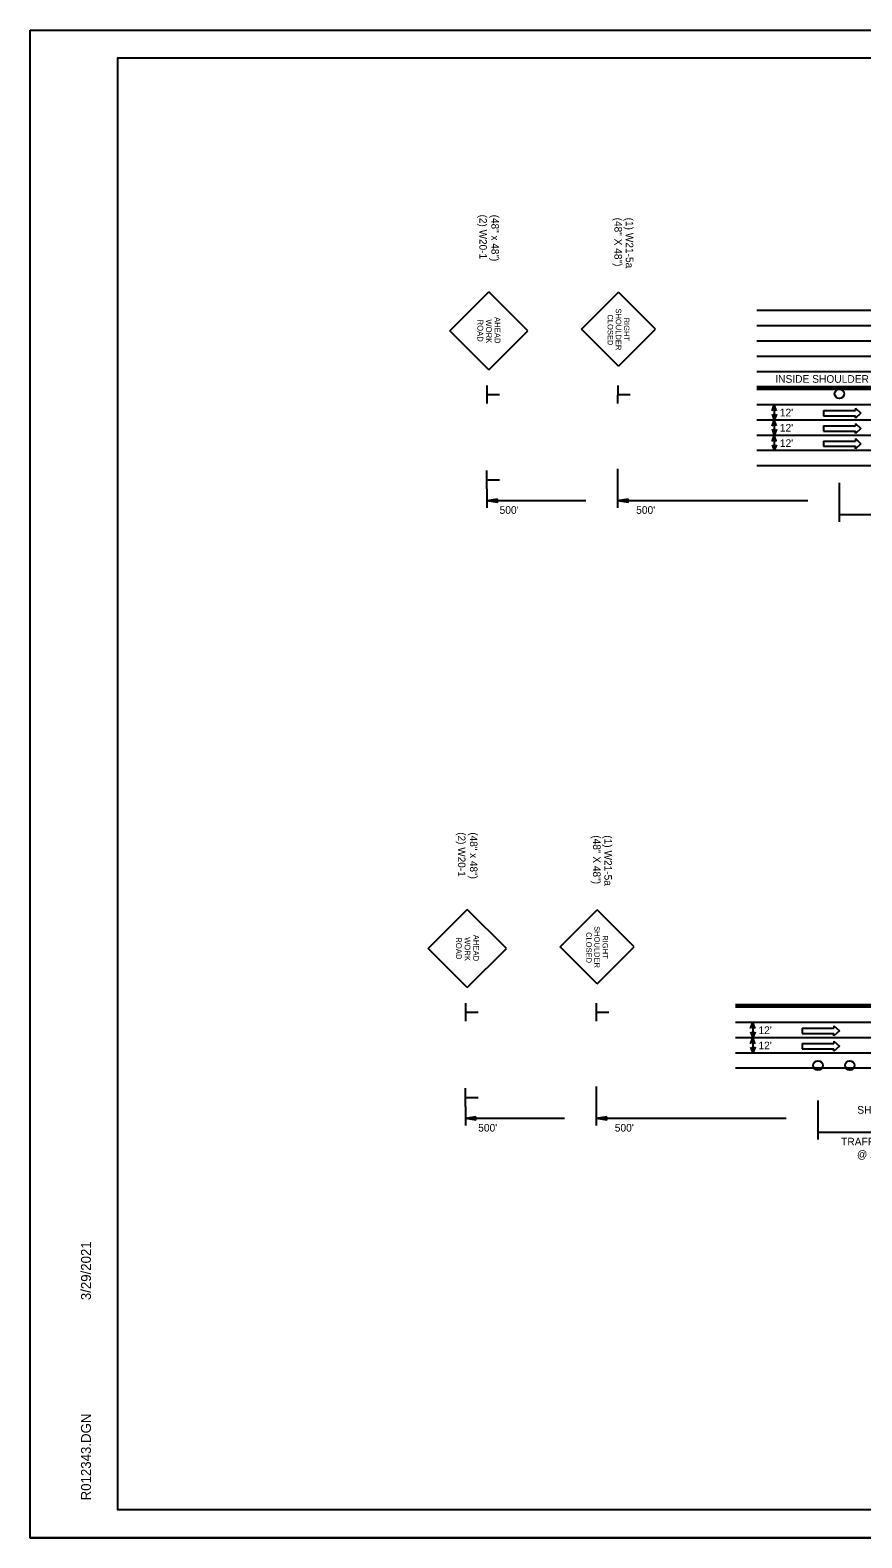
# Model space of a CAD drawing. Extents: x 1397271 to 1411271, y 376395 to 377888.
# Drawn here: x 1408938 to 1409762, y 376395 to 377888 of the extents above; entities that cross this region are included whole.
import ezdxf

# ---------------------------------------------------------------- set-up
doc = ezdxf.new("R2010")
doc.units = 0
for name, color, linetype in [('Default', 7, 'Continuous'), ('R_Border', 7, 'Continuous'), ('R_Dimension', 7, 'Continuous'), ('R_Horz Alg', 7, 'Continuous'), ('R_MOT', 7, 'Continuous'), ('R_No Plot', 7, 'Continuous')]:
    doc.layers.add(name, color=color, linetype=linetype)

msp = doc.modelspace()

# ---------------------------------------------------------------- linework, layer by layer
at = {"layer": 'Default'}
for p, q in [((1409400.8, 377423.3), (1409390.5, 377421.7)), ((1409400.8, 377420.2), (1409390.5, 377421.7)), ((1409400.8, 377423.1), (1409392.2, 377421.7)), ((1409400.8, 377420.5), (1409392.2, 377421.7)), ((1409400.8, 377422.8), (1409394, 377421.8)), ((1409400.8, 377420.8), (1409394, 377421.8)), ((1409400.8, 377422.6), (1409395.7, 377421.8)), ((1409400.8, 377421), (1409395.7, 377421.8)), ((1409400.8, 377422.3), (1409397.4, 377421.8)), ((1409400.8, 377421.3), (1409397.4, 377421.8)), ((1409400.8, 377422), (1409399.2, 377421.8)), ((1409400.8, 377421.6), (1409399.2, 377421.8)), ((1409400.8, 377420.2), (1409400.8, 377423.3)), ((1409530.3, 377423.3), (1409519.9, 377421.7)), ((1409530.3, 377420.2), (1409519.9, 377421.7)), ((1409530.3, 377423.1), (1409521.7, 377421.7)), ((1409530.3, 377420.5), (1409521.7, 377421.7)), ((1409530.3, 377422.8), (1409523.5, 377421.8)), ((1409530.3, 377420.8), (1409523.5, 377421.8)), ((1409530.3, 377422.6), (1409525.2, 377421.8)), ((1409530.3, 377421), (1409525.2, 377421.8)), ((1409530.3, 377422.3), (1409526.9, 377421.8)), ((1409530.3, 377421.3), (1409526.9, 377421.8)), ((1409530.3, 377422), (1409528.7, 377421.8)), ((1409530.3, 377421.6), (1409528.7, 377421.8)), ((1409530.3, 377420.2), (1409530.3, 377423.3)), ((1409379.6, 376811.5), (1409369.3, 376809.9)), ((1409379.6, 376808.4), (1409369.3, 376809.9)), ((1409379.6, 376811.3), (1409371, 376809.9)), ((1409379.6, 376808.7), (1409371, 376809.9)), ((1409379.6, 376811), (1409372.8, 376809.9)), ((1409379.6, 376809), (1409372.8, 376809.9)), ((1409379.6, 376810.8), (1409374.5, 376810)), ((1409379.6, 376809.2), (1409374.5, 376810)), ((1409379.6, 376810.5), (1409376.2, 376810)), ((1409379.6, 376809.5), (1409376.2, 376810)), ((1409379.6, 376810.2), (1409378, 376810)), ((1409379.6, 376809.7), (1409378, 376810)), ((1409379.6, 376808.4), (1409379.6, 376811.5)), ((1409509.1, 376811.5), (1409498.7, 376809.9)), ((1409509.1, 376808.4), (1409498.7, 376809.9)), ((1409509.1, 376811.3), (1409500.5, 376809.9)), ((1409509.1, 376808.7), (1409500.5, 376809.9)), ((1409509.1, 376811), (1409502.2, 376809.9)), ((1409509.1, 376809), (1409502.2, 376809.9)), ((1409509.1, 376810.8), (1409504, 376810)), ((1409509.1, 376809.2), (1409504, 376810)), ((1409509.1, 376810.5), (1409505.7, 376810)), ((1409509.1, 376809.5), (1409505.7, 376810)), ((1409509.1, 376810.2), (1409507.4, 376810)), ((1409509.1, 376809.7), (1409507.4, 376810)), ((1409509.1, 376808.4), (1409509.1, 376811.5))]:
    msp.add_line(p, q, dxfattribs=at)
at = {"layer": 'R_Border'}
for p, q in [((1409024.8, 377860.7), (1411238.1, 377860.7)), ((1409024.8, 376422.5), (1409024.8, 377860.7)), ((1409024.8, 376422.5), (1409024.8, 376422.5)), ((1411238.1, 376422.5), (1409024.8, 376422.5))]:
    msp.add_line(p, q, dxfattribs=at)
at = {"layer": 'R_Dimension'}
for p, q in [((1409673, 377511), (1409675.1, 377516.9)), ((1409675.1, 377516.9), (1409675.1, 377471.5)), ((1409677.3, 377511), (1409675.1, 377516.9)), ((1409672.9, 377507.7), (1409675.1, 377501.8)), ((1409673, 377495.8), (1409675.1, 377501.8)), ((1409677.2, 377507.7), (1409675.1, 377501.8)), ((1409677.3, 377495.9), (1409675.1, 377501.8)), ((1409672.9, 377492.6), (1409675.1, 377486.6)), ((1409673, 377480.7), (1409675.1, 377486.6)), ((1409677.2, 377492.6), (1409675.1, 377486.6)), ((1409677.3, 377480.7), (1409675.1, 377486.6)), ((1409672.9, 377477.4), (1409675.1, 377471.5)), ((1409677.2, 377477.4), (1409675.1, 377471.5)), ((1409519.9, 377453.4), (1409519.9, 377414.9)), ((1409739.5, 377439.7), (1409739.5, 377401.1)), ((1409390.5, 377433.8), (1409390.5, 377414.9)), ((1409488.4, 377421.7), (1409390.5, 377421.7)), ((1409708.2, 377421.7), (1409519.9, 377421.7)), ((1410117.6, 377408), (1409739.5, 377408)), ((1409651.7, 376899.2), (1409653.9, 376905.1)), ((1409653.9, 376905.1), (1409653.9, 376874.8)), ((1409656.1, 376899.2), (1409653.9, 376905.1)), ((1409651.7, 376895.9), (1409653.9, 376890)), ((1409651.7, 376884), (1409653.9, 376890)), ((1409656, 376895.9), (1409653.9, 376890)), ((1409656.1, 376884), (1409653.9, 376890)), ((1409651.7, 376880.7), (1409653.9, 376874.8)), ((1409656, 376880.8), (1409653.9, 376874.8)), ((1409498.7, 376841.6), (1409498.7, 376803.1)), ((1409718.3, 376827.9), (1409718.3, 376789.3)), ((1409369.3, 376822), (1409369.3, 376803.1)), ((1409467.2, 376809.9), (1409369.3, 376809.9)), ((1409687, 376809.9), (1409498.7, 376809.9)), ((1410373.8, 376796.2), (1409718.3, 376796.2))]:
    msp.add_line(p, q, dxfattribs=at)
at = {"layer": 'R_Horz Alg'}
for p, q in [((1410680, 377610.2), (1409657.9, 377610.2)), ((1410680, 377595.1), (1409657.9, 377595.1)), ((1410680, 377579.9), (1409657.9, 377579.9)), ((1410680, 377564.8), (1409657.9, 377564.8)), ((1410680, 377549.7), (1409657.9, 377549.7)), ((1409991.6, 377534.6), (1409657.9, 377534.6)), ((1410680, 377533.3), (1409657.9, 377533.3)), ((1409991.6, 377532), (1409657.9, 377532)), ((1410680, 377516.9), (1409657.9, 377516.9)), ((1410680, 377501.8), (1409657.9, 377501.8)), ((1410680, 377486.6), (1409657.9, 377486.6)), ((1410680, 377471.5), (1409657.9, 377471.5)), ((1410680, 377456.4), (1409657.9, 377456.4)), ((1409970.4, 376922.7), (1409636.7, 376922.7)), ((1410658.8, 376921.5), (1409636.7, 376921.5)), ((1409970.4, 376920.2), (1409636.7, 376920.2)), ((1410658.8, 376905.1), (1409636.7, 376905.1)), ((1410658.8, 376890), (1409636.7, 376890)), ((1410658.8, 376874.8), (1409636.7, 376874.8)), ((1410091.5, 376859.7), (1409636.7, 376859.7))]:
    msp.add_line(p, q, dxfattribs=at)
at = {"layer": 'R_MOT'}
for p, q in [((1409353.6, 377590.2), (1409392.3, 377628.8)), ((1409430.9, 377590.2), (1409392.3, 377628.8)), ((1409484.3, 377591.9), (1409520.9, 377628.6)), ((1409557.6, 377591.9), (1409520.9, 377628.6)), ((1409392.3, 377551.5), (1409353.6, 377590.2)), ((1409392.3, 377551.5), (1409430.9, 377590.2)), ((1409520.9, 377555.3), (1409484.3, 377591.9)), ((1409520.9, 377555.3), (1409557.6, 377591.9)), ((1409390.5, 377536), (1409390.4, 377518.1)), ((1409520, 377536), (1409519.9, 377518.1)), ((1409390.4, 377527.1), (1409402.9, 377527)), ((1409520, 377527.1), (1409532.5, 377527)), ((1409723.9, 377511.1), (1409755.4, 377511.1)), ((1409723.9, 377511.1), (1409723.9, 377506.1)), ((1409723.9, 377506.1), (1409755.4, 377506.1)), ((1409755.4, 377513.6), (1409760.9, 377508.6)), ((1409755.4, 377513.6), (1409755.4, 377511.1)), ((1409760.9, 377508.6), (1409755.4, 377503.6)), ((1409755.4, 377503.6), (1409755.4, 377506.1)), ((1409723.9, 377496), (1409755.4, 377496)), ((1409723.9, 377496), (1409723.9, 377490.9)), ((1409723.9, 377490.9), (1409755.4, 377490.9)), ((1409755.4, 377498.5), (1409760.9, 377493.5)), ((1409755.4, 377498.5), (1409755.4, 377496)), ((1409760.9, 377493.5), (1409755.4, 377488.4)), ((1409755.4, 377488.4), (1409755.4, 377490.9)), ((1409723.9, 377480.9), (1409755.4, 377480.9)), ((1409723.9, 377480.9), (1409723.9, 377475.8)), ((1409723.9, 377475.8), (1409755.4, 377475.8)), ((1409755.4, 377483.4), (1409760.9, 377478.3)), ((1409755.4, 377483.4), (1409755.4, 377480.9)), ((1409760.9, 377478.3), (1409755.4, 377473.3)), ((1409755.4, 377473.3), (1409755.4, 377475.8)), ((1409390.5, 377433.8), (1409390.4, 377451.7)), ((1409390.4, 377442.7), (1409402.9, 377442.7)), ((1409332.4, 376978.4), (1409371, 377017)), ((1409409.7, 376978.4), (1409371, 377017)), ((1409463.1, 376980.1), (1409499.7, 377016.7)), ((1409536.4, 376980.1), (1409499.7, 377016.7)), ((1409371, 376939.7), (1409332.4, 376978.4)), ((1409371, 376939.7), (1409409.7, 376978.4)), ((1409499.7, 376943.4), (1409463.1, 376980.1)), ((1409499.7, 376943.4), (1409536.4, 376980.1)), ((1409369.3, 376924.2), (1409369.2, 376906.3)), ((1409498.8, 376924.2), (1409498.7, 376906.3)), ((1409369.2, 376915.3), (1409381.7, 376915.2)), ((1409498.8, 376915.3), (1409511.2, 376915.2)), ((1409702.7, 376899.3), (1409734.2, 376899.3)), ((1409702.7, 376899.3), (1409702.7, 376894.3)), ((1409702.7, 376894.3), (1409734.2, 376894.3)), ((1409734.2, 376901.8), (1409739.7, 376896.8)), ((1409734.2, 376901.8), (1409734.2, 376899.3)), ((1409739.7, 376896.8), (1409734.2, 376891.7)), ((1409734.2, 376891.7), (1409734.2, 376894.3)), ((1409702.7, 376884.2), (1409734.2, 376884.2)), ((1409702.7, 376884.2), (1409702.7, 376879.1)), ((1409702.7, 376879.1), (1409734.2, 376879.1)), ((1409734.2, 376886.7), (1409739.7, 376881.7)), ((1409734.2, 376886.7), (1409734.2, 376884.2)), ((1409739.7, 376881.7), (1409734.2, 376876.6)), ((1409734.2, 376876.6), (1409734.2, 376879.1)), ((1409369.3, 376822), (1409369.2, 376839.9)), ((1409369.2, 376830.9), (1409381.7, 376830.9))]:
    msp.add_line(p, q, dxfattribs=at)
for centre in [(1409739.6, 377527.8), (1409718.4, 376862.5), (1409749.9, 376862.5)]:
    msp.add_circle(centre, 4.73, dxfattribs=at)
at = {"layer": 'R_No Plot'}
for p, q in [((1408938, 377888), (1411271.4, 377888)), ((1408938, 376394.6), (1411271.4, 376394.6))]:
    msp.add_line(p, q, dxfattribs=at)
for points in [[(1408938, 377888), (1411271.4, 377888), (1411271.4, 376394.6), (1408938, 376394.6)], [(1410662.3, 377860.7), (1410662.3, 377791.6), (1410912.4, 377791.6), (1410912.4, 377771.1), (1411074.8, 377771.1), (1411074.8, 377600.8), (1411238.1, 377600.8), (1411238.1, 376422.5), (1409024.8, 376422.5), (1409024.8, 377860.7)]]:
    msp.add_lwpolyline(points, close=True, dxfattribs=at)

# ---------------------------------------------------------------- texts
at = {"layer": 'R_Border'}
for s, p in [('3/29/2021', (1408998.2, 376630)), ('R012343.DGN', (1408998.2, 376431.7))]:
    msp.add_text(s, height=9.8, rotation=90, dxfattribs=at).set_placement(p)
at = {"layer": 'R_Dimension'}
for s, height, p in [("INSIDE SHOULDER LESS THAN 18'", 7.565, (1409676.1, 377538.7)), ("12'", 7.57, (1409680.6, 377505.4)), ("12'", 7.57, (1409680.6, 377490.3)), ("12'", 7.57, (1409680.6, 377475.1)), ("500'", 7.57, (1409403, 377408.9)), ("500'", 7.57, (1409538.3, 377408.9)), ("12'", 7.57, (1409659.4, 376893.6)), ("12'", 7.57, (1409659.4, 376878.5)), ('SHOULDER', 7.57, (1409757.3, 376814.7)), ("500'", 7.57, (1409381.8, 376797)), ("500'", 7.57, (1409517.1, 376797)), ('TRAFFIC DRUMS ', 7.565, (1409741.3, 376783.3)), ("@ 25' O.C.", 7.57, (1409757, 376770.7))]:
    msp.add_text(s, height=height, dxfattribs=at).set_placement(p)
at = {"layer": 'R_MOT'}
for s, height, rotation, p in [('(2) W20-1', 7.41, 270, (1409383, 377705.3)), ('(48" x 48")', 7.415, 270, (1409394.9, 377705.2)), ('(48" X 48")', 7.5, 270, (1409516.8, 377702.3)), ('(1) W21-5a', 7.5, 270, (1409528, 377702.3)), ('CLOSED', 5.4, 270.0006, (1409510, 377606.4)), ('SHOULDER', 5.4, 270, (1409518.1, 377612.3)), ('ROAD', 5.69, 269.9996, (1409381.1, 377601.3)), ('WORK', 5.69, 270, (1409389.6, 377601.5)), ('AHEAD', 5.69, 269.9994, (1409398.1, 377603.8)), ('RIGHT', 5.4, 270.0004, (1409526.2, 377603.2)), ('(2) W20-1', 7.41, 270, (1409361.8, 377093.5)), ('(48" x 48")', 7.415, 270, (1409373.7, 377093.4)), ('(48" X 48")', 7.5, 270, (1409495.6, 377090.5)), ('(1) W21-5a', 7.5, 270, (1409506.8, 377090.5)), ('AHEAD', 5.69, 269.9994, (1409376.9, 376992)), ('CLOSED', 5.4, 270.0006, (1409488.8, 376994.6)), ('SHOULDER', 5.4, 270, (1409496.9, 377000.5)), ('ROAD', 5.69, 269.9996, (1409359.8, 376989.5)), ('WORK', 5.69, 270, (1409368.4, 376989.6)), ('RIGHT', 5.4, 270.0004, (1409505, 376991.4))]:
    msp.add_text(s, height=height, rotation=rotation, dxfattribs=at).set_placement(p)

doc.saveas('drawing.dxf')
